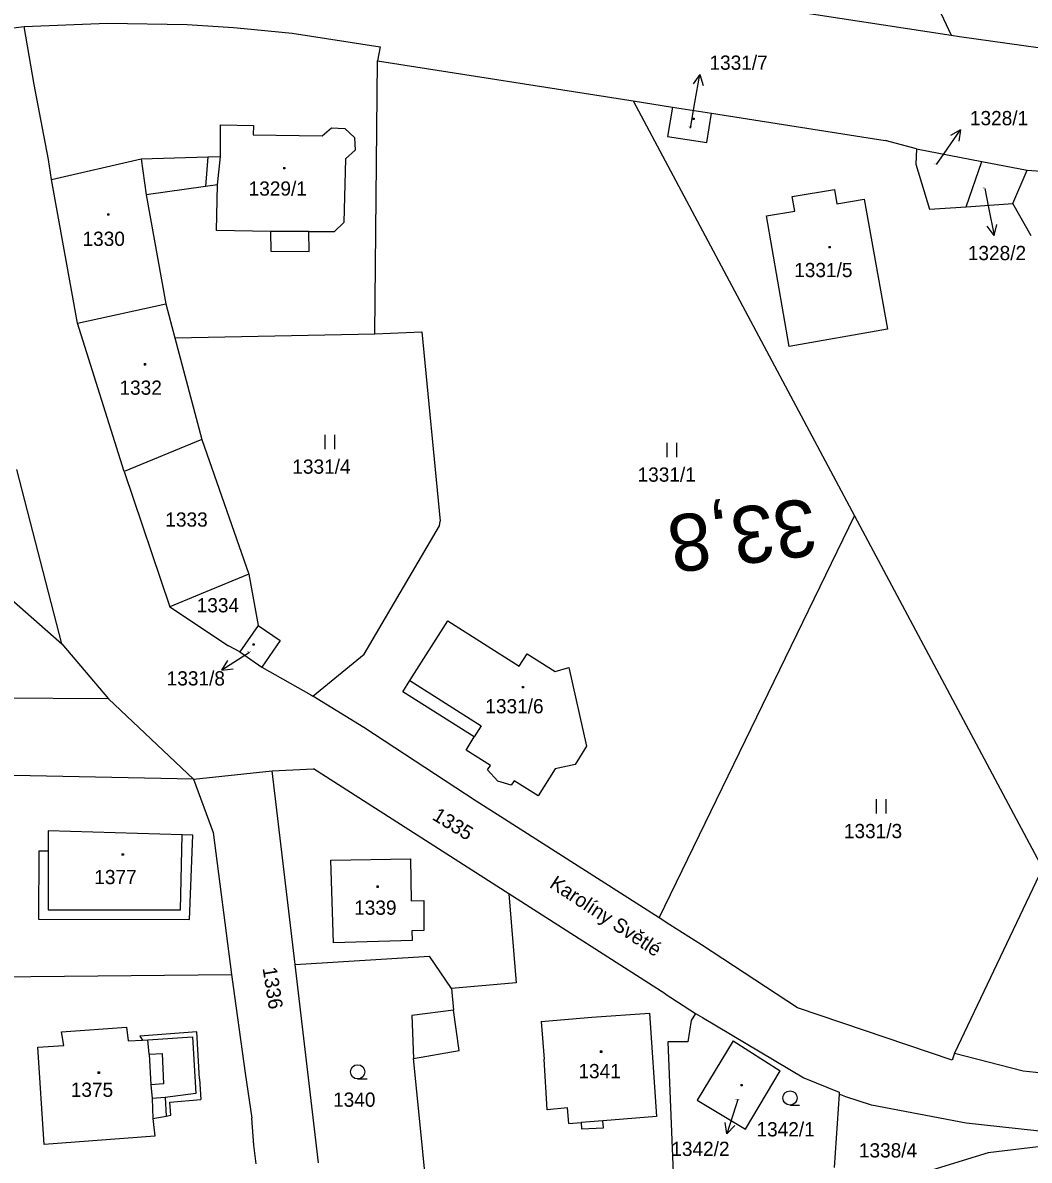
# Model space of a CAD drawing. Extents: x -805011 to -803920, y -1150790 to -1150234.
# Drawn here: x -804706.8 to -804600.8, y -1150469 to -1150349.3 of the extents above; entities that cross this region are included whole.
import ezdxf

# ---------------------------------------------------------------- set-up
doc = ezdxf.new("R2010")
doc.units = 0
for name, color, linetype in [('Default', 7, 'Continuous'), ('kilometráž - vrstava 7', 7, 'Continuous'), ('kn_celek - Cisla parcel pomocna', 7, 'Continuous'), ('kn_celek - Cisla pozemkovych parcel', 7, 'Continuous'), ('kn_celek - Cisla stavebnich parcel', 7, 'Continuous'), ('kn_celek - Dalsi prvky mapy popis', 7, 'Continuous'), ('kn_celek - Hranice parcel', 7, 'Continuous'), ('kn_celek - Vnitrni kresby', 7, 'Continuous'), ('kn_celek - Znacky budov', 7, 'Continuous'), ('kn_celek - Znacky kultur', 7, 'Continuous')]:
    doc.layers.add(name, color=color, linetype=linetype)

# ---------------------------------------------------------------- blocks, each defined once
blk = doc.blocks.new('306')
at = {"layer": 'Default'}
for p, q in [((-5.2, 0), (-5.2, 15)), ((4.8, 0), (4.8, 15))]:
    blk.add_line(p, q, dxfattribs=at)
blk = doc.blocks.new('304')
at = {"layer": 'Default'}
blk.add_line((-0.1, 0), (9.9, 0), dxfattribs=at)
blk.add_circle((-0.1, 7.5), 7.5, dxfattribs=at)
blk = doc.blocks.new('402')
at = {"layer": 'Default'}
for p, q in [((-0.8, 0.8), (0.7, 0.8)), ((-0.8, 0.8), (-0.8, -0.7)), ((0.7, 0.8), (0.7, -0.7)), ((0.7, -0.7), (-0.8, -0.7))]:
    blk.add_line(p, q, dxfattribs=at)
blk = doc.blocks.new('Z61')
at = {"layer": 'Default'}
for p, q in [((0, 0), (30, 0)), ((30, 0), (19.2, 5.3)), ((30, 0), (19.2, -5.3))]:
    blk.add_line(p, q, dxfattribs=at)

msp = doc.modelspace()

# ---------------------------------------------------------------- linework, layer by layer
at = {"layer": 'kn_celek - Cisla parcel pomocna'}
for p, q in [((-804636.49, -1150360.35), (-804636.01, -1150357.67)), ((-804610.59, -1150364.2), (-804609.77, -1150363.02)), ((-804605.49, -1150366.73), (-804605.1, -1150368.71)), ((-804682.9, -1150415.54), (-804683.3, -1150415.8)), ((-804631.49, -1150462.6), (-804631.74, -1150463.37))]:
    msp.add_line(p, q, dxfattribs=at)
at = {"layer": 'kn_celek - Hranice parcel'}
for p, q in [((-804636.63, -1150346.35), (-804609.04, -1150350.57)), ((-804610.97, -1150346.41), (-804609.04, -1150350.57)), ((-804716.89, -1150350.96), (-804706.62, -1150349.66)), ((-804706.62, -1150349.66), (-804697.86, -1150349.31)), ((-804705.57, -1150355.76), (-804706.62, -1150349.66)), ((-804697.86, -1150349.31), (-804689.48, -1150349.47)), ((-804689.48, -1150349.47), (-804684.61, -1150349.77)), ((-804684.61, -1150349.77), (-804683.48, -1150349.86)), ((-804683.48, -1150349.86), (-804678.43, -1150350.37)), ((-804678.43, -1150350.37), (-804669.14, -1150351.82)), ((-804609.04, -1150350.57), (-804608.15, -1150350.71)), ((-804608.15, -1150350.71), (-804597.6, -1150352.18)), ((-804669.14, -1150351.82), (-804669.43, -1150353.29)), ((-804669.7, -1150382.01), (-804669.43, -1150353.29)), ((-804669.43, -1150353.29), (-804642.5, -1150357.5)), ((-804705.03, -1150358.73), (-804705.57, -1150355.76)), ((-804642.5, -1150357.5), (-804638.39, -1150358.14)), ((-804642.5, -1150357.5), (-804619.21, -1150401.17)), ((-804638.39, -1150358.14), (-804638.89, -1150361.24)), ((-804638.39, -1150358.14), (-804634.27, -1150358.79)), ((-804704.08, -1150363.65), (-804705.03, -1150358.73)), ((-804634.75, -1150361.89), (-804634.27, -1150358.79)), ((-804634.27, -1150358.79), (-804615.97, -1150361.65)), ((-804638.89, -1150361.24), (-804634.75, -1150361.89)), ((-804612.68, -1150362.53), (-804615.97, -1150361.65)), ((-804612.68, -1150362.53), (-804612.74, -1150364.14)), ((-804612.68, -1150362.53), (-804605.79, -1150363.86)), ((-804703.74, -1150365.76), (-804704.08, -1150363.65)), ((-804703.74, -1150365.76), (-804694.3, -1150363.6)), ((-804694.3, -1150363.6), (-804693.79, -1150367.39)), ((-804612.74, -1150364.14), (-804611.3, -1150368.91)), ((-804607.45, -1150368.65), (-804605.79, -1150363.86)), ((-804605.79, -1150363.86), (-804601.03, -1150364.78)), ((-804602.54, -1150368.31), (-804601.03, -1150364.78)), ((-804601.03, -1150364.78), (-804583.56, -1150366.12)), ((-804701, -1150380.9), (-804703.74, -1150365.76)), ((-804693.79, -1150367.39), (-804691.72, -1150378.86)), ((-804625.77, -1150367.55), (-804621.33, -1150366.83)), ((-804625.5, -1150369.09), (-804625.77, -1150367.55)), ((-804621.33, -1150366.83), (-804621.06, -1150368.32)), ((-804621.06, -1150368.32), (-804618.19, -1150367.84)), ((-804618.19, -1150367.84), (-804615.74, -1150381.54)), ((-804628.48, -1150369.59), (-804625.5, -1150369.09)), ((-804611.3, -1150368.91), (-804607.45, -1150368.65)), ((-804607.45, -1150368.65), (-804602.54, -1150368.31)), ((-804600.6, -1150371.69), (-804602.54, -1150368.31)), ((-804626.08, -1150383.35), (-804628.48, -1150369.59)), ((-804701, -1150380.9), (-804691.72, -1150378.86)), ((-804691.72, -1150378.86), (-804690.78, -1150382.42)), ((-804696.11, -1150396.49), (-804701, -1150380.9)), ((-804690.78, -1150382.42), (-804669.7, -1150382.01)), ((-804669.7, -1150382.01), (-804664.75, -1150381.81)), ((-804664.75, -1150381.81), (-804662.85, -1150401.75)), ((-804615.74, -1150381.54), (-804626.08, -1150383.35)), ((-804690.78, -1150382.42), (-804687.93, -1150393.14)), ((-804687.93, -1150393.14), (-804696.11, -1150396.49)), ((-804687.93, -1150393.14), (-804682.98, -1150407.3)), ((-804702.68, -1150414.65), (-804707.42, -1150396.29)), ((-804696.11, -1150396.49), (-804691.29, -1150410.75)), ((-804639.79, -1150443.5), (-804619.21, -1150401.17)), ((-804619.21, -1150401.17), (-804599.42, -1150438.27)), ((-804670.83, -1150415.74), (-804662.92, -1150402.21)), ((-804662.92, -1150402.21), (-804662.85, -1150401.75)), ((-804682.98, -1150407.3), (-804684.18, -1150407.8)), ((-804682.98, -1150407.3), (-804681.98, -1150412.71)), ((-804684.18, -1150407.8), (-804688.58, -1150409.63)), ((-804708.84, -1150409.22), (-804702.68, -1150414.65)), ((-804688.58, -1150409.63), (-804691.29, -1150410.75)), ((-804691.29, -1150410.75), (-804685.13, -1150414.86)), ((-804666.02, -1150418.51), (-804662.04, -1150412.23)), ((-804662.04, -1150412.23), (-804654.51, -1150417.01)), ((-804681.98, -1150412.71), (-804683.93, -1150415.5)), ((-804681.98, -1150412.71), (-804679.67, -1150414.3)), ((-804702.68, -1150414.65), (-804697.76, -1150420.42)), ((-804679.67, -1150414.3), (-804681.62, -1150417.09)), ((-804683.93, -1150415.5), (-804685.13, -1150414.86)), ((-804683.93, -1150415.5), (-804681.62, -1150417.09)), ((-804676.25, -1150420.14), (-804670.83, -1150415.74)), ((-804654.51, -1150417.01), (-804653.68, -1150415.69)), ((-804653.68, -1150415.69), (-804650.71, -1150417.57)), ((-804681.62, -1150417.09), (-804676.44, -1150420.03)), ((-804650.71, -1150417.57), (-804649.28, -1150417.14)), ((-804649.28, -1150417.14), (-804647.42, -1150425.41)), ((-804666.77, -1150419.69), (-804666.02, -1150418.51)), ((-804697.76, -1150420.42), (-804721.63, -1150420.28)), ((-804688.79, -1150428.9), (-804697.76, -1150420.42)), ((-804676.44, -1150420.03), (-804676.25, -1150420.14)), ((-804670.86, -1150423.46), (-804676.25, -1150420.14)), ((-804659.26, -1150424.45), (-804666.77, -1150419.69)), ((-804659.05, -1150431.22), (-804670.86, -1150423.46)), ((-804660.1, -1150425.82), (-804659.26, -1150424.45)), ((-804647.42, -1150425.41), (-804648.63, -1150427.35)), ((-804657.55, -1150427.45), (-804660.1, -1150425.82)), ((-804680.52, -1150428), (-804676.16, -1150427.79)), ((-804655.59, -1150440.95), (-804676.16, -1150427.79)), ((-804657.86, -1150427.92), (-804657.55, -1150427.45)), ((-804650.71, -1150427.79), (-804652.53, -1150430.65)), ((-804648.63, -1150427.35), (-804650.71, -1150427.79)), ((-804688.79, -1150428.9), (-804710.95, -1150428.42)), ((-804688.79, -1150428.9), (-804680.52, -1150428)), ((-804688.79, -1150428.9), (-804686.75, -1150434.51)), ((-804678.11, -1150448.38), (-804680.52, -1150428)), ((-804656.76, -1150429.09), (-804657.86, -1150427.92)), ((-804655.06, -1150429.05), (-804655.35, -1150429.51)), ((-804652.53, -1150430.65), (-804655.06, -1150429.05)), ((-804655.35, -1150429.51), (-804656.76, -1150429.09)), ((-804656.45, -1150432.87), (-804659.05, -1150431.22)), ((-804639.79, -1150443.5), (-804656.45, -1150432.87)), ((-804704.09, -1150434.34), (-804704.1, -1150436.47)), ((-804690.01, -1150434.74), (-804704.09, -1150434.34)), ((-804688.87, -1150434.77), (-804690.01, -1150434.74)), ((-804689.21, -1150443.66), (-804688.87, -1150434.77)), ((-804686.75, -1150434.51), (-804684.79, -1150449.44)), ((-804705.1, -1150436.47), (-804705.11, -1150443.63)), ((-804704.1, -1150436.47), (-804705.1, -1150436.47)), ((-804599.42, -1150438.27), (-804608.69, -1150457.72)), ((-804639.15, -1150451.48), (-804655.59, -1150440.95)), ((-804655.59, -1150440.95), (-804654.84, -1150450.33)), ((-804705.11, -1150443.63), (-804689.21, -1150443.66)), ((-804638.64, -1150444.23), (-804639.79, -1150443.5)), ((-804635.32, -1150446.34), (-804638.64, -1150444.23)), ((-804625.2, -1150452.95), (-804635.32, -1150446.34)), ((-804678.11, -1150448.38), (-804663.96, -1150447.53)), ((-804661.65, -1150450.93), (-804663.96, -1150447.53)), ((-804675.65, -1150469.27), (-804678.11, -1150448.38)), ((-804710.75, -1150449.7), (-804684.79, -1150449.44)), ((-804684.79, -1150449.44), (-804683.38, -1150459.83)), ((-804654.84, -1150450.33), (-804661.65, -1150450.93)), ((-804661.65, -1150450.93), (-804661.44, -1150453.2)), ((-804639.15, -1150451.48), (-804635.94, -1150453.54)), ((-804608.93, -1150458.48), (-804625.2, -1150452.95)), ((-804661.44, -1150453.2), (-804665.82, -1150453.75)), ((-804665.82, -1150453.75), (-804665.63, -1150458.28)), ((-804635.94, -1150453.54), (-804636.41, -1150454.28)), ((-804635.94, -1150453.54), (-804635.23, -1150453.99)), ((-804635.23, -1150453.99), (-804624.56, -1150460.33)), ((-804636.41, -1150454.28), (-804636.77, -1150456.54)), ((-804636.77, -1150456.54), (-804638.87, -1150456.55)), ((-804638.87, -1150456.55), (-804638.3, -1150470.31)), ((-804631.98, -1150456.42), (-804635.78, -1150462.69)), ((-804631.98, -1150456.42), (-804627.05, -1150459.6)), ((-804608.69, -1150457.72), (-804608.93, -1150458.48)), ((-804608.69, -1150457.72), (-804601.47, -1150459.58)), ((-804664.84, -1150466.32), (-804665.63, -1150458.28)), ((-804683.38, -1150459.83), (-804682.67, -1150464.56)), ((-804630.7, -1150465.73), (-804627.05, -1150459.6)), ((-804601.47, -1150459.58), (-804584.21, -1150461.47)), ((-804624.56, -1150460.33), (-804620.82, -1150461.83)), ((-804620.84, -1150462.06), (-804621.34, -1150469.78)), ((-804620.82, -1150461.83), (-804620.84, -1150462.06)), ((-804620.14, -1150462.34), (-804620.84, -1150462.06)), ((-804617.42, -1150463.22), (-804620.14, -1150462.34)), ((-804635.78, -1150462.69), (-804630.7, -1150465.73)), ((-804607.47, -1150465.11), (-804617.42, -1150463.22)), ((-804682.45, -1150467.4), (-804682.67, -1150464.56)), ((-804592.74, -1150466.72), (-804607.47, -1150465.11)), ((-804664.29, -1150471.93), (-804664.84, -1150466.32)), ((-804592.74, -1150466.72), (-804605.13, -1150468.22)), ((-804682.2, -1150469.39), (-804682.45, -1150467.4)), ((-804605.13, -1150468.22), (-804622.06, -1150473.4))]:
    msp.add_line(p, q, dxfattribs=at)
at = {"layer": 'kn_celek - Vnitrni kresby'}
for p, q in [((-804685.97, -1150363.36), (-804685.96, -1150360.02)), ((-804685.96, -1150360.02), (-804682.49, -1150360.08)), ((-804682.49, -1150360.08), (-804682.51, -1150361.06)), ((-804675.26, -1150361.17), (-804674.26, -1150360.32)), ((-804674.26, -1150360.32), (-804672.87, -1150360.41)), ((-804672.87, -1150360.41), (-804671.87, -1150361.34)), ((-804682.51, -1150361.06), (-804675.26, -1150361.17)), ((-804671.87, -1150361.34), (-804671.77, -1150362.69)), ((-804671.77, -1150362.69), (-804672.8, -1150363.61)), ((-804694.3, -1150363.6), (-804687.28, -1150363.4)), ((-804687.28, -1150363.4), (-804687.53, -1150366.51)), ((-804687.28, -1150363.4), (-804685.97, -1150363.36)), ((-804686.26, -1150366.33), (-804685.97, -1150363.36)), ((-804672.8, -1150363.61), (-804672.99, -1150370.31)), ((-804687.53, -1150366.51), (-804693.79, -1150367.39)), ((-804686.26, -1150366.33), (-804687.53, -1150366.51)), ((-804686.37, -1150371.14), (-804686.26, -1150366.33)), ((-804672.99, -1150370.31), (-804673.97, -1150371.26)), ((-804680.69, -1150371.24), (-804686.37, -1150371.14)), ((-804676.66, -1150371.25), (-804680.69, -1150371.24)), ((-804680.69, -1150371.24), (-804680.67, -1150373.32)), ((-804676.63, -1150373.35), (-804676.66, -1150371.25)), ((-804676.66, -1150371.25), (-804673.97, -1150371.26)), ((-804680.67, -1150373.32), (-804676.63, -1150373.35)), ((-804666.02, -1150418.51), (-804658.51, -1150423.27)), ((-804658.51, -1150423.27), (-804659.26, -1150424.45)), ((-804690.19, -1150442.65), (-804690.01, -1150434.74)), ((-804704.1, -1150436.47), (-804704.12, -1150442.63)), ((-804674.33, -1150437.42), (-804665.97, -1150437.27)), ((-804674.08, -1150446.1), (-804674.33, -1150437.42)), ((-804665.97, -1150437.27), (-804665.89, -1150441.68)), ((-804665.89, -1150441.68), (-804664.55, -1150441.65)), ((-804664.55, -1150441.65), (-804664.56, -1150444.81)), ((-804704.12, -1150442.63), (-804690.19, -1150442.65)), ((-804664.56, -1150444.81), (-804665.81, -1150444.84)), ((-804665.81, -1150444.84), (-804665.78, -1150445.86)), ((-804665.78, -1150445.86), (-804674.08, -1150446.1)), ((-804660.82, -1150457.45), (-804661.44, -1150453.2)), ((-804652.21, -1150454.41), (-804646.87, -1150453.95)), ((-804646.87, -1150453.95), (-804640.78, -1150453.51)), ((-804640.78, -1150453.51), (-804640.04, -1150464.41)), ((-804702.69, -1150455.5), (-804695.87, -1150455)), ((-804695.87, -1150455), (-804695.69, -1150456.44)), ((-804652.21, -1150454.41), (-804651.89, -1150458.37)), ((-804702.47, -1150456.92), (-804702.69, -1150455.5)), ((-804695.69, -1150456.44), (-804694.16, -1150456.37)), ((-804688.44, -1150455.5), (-804694.45, -1150455.95)), ((-804694.45, -1150455.95), (-804694.16, -1150456.37)), ((-804694.16, -1150456.37), (-804693.61, -1150456.33)), ((-804693.61, -1150456.33), (-804688.91, -1150456.02)), ((-804693.48, -1150457.82), (-804693.61, -1150456.33)), ((-804688.91, -1150456.02), (-804688.56, -1150461.98)), ((-804688.16, -1150460.44), (-804688.44, -1150455.5)), ((-804705.18, -1150457.11), (-804702.47, -1150456.92)), ((-804704.52, -1150467.35), (-804705.18, -1150457.11)), ((-804693.48, -1150457.82), (-804692.1, -1150457.75)), ((-804692.1, -1150457.75), (-804691.95, -1150460.97)), ((-804665.63, -1150458.28), (-804660.82, -1150457.45)), ((-804693.48, -1150457.82), (-804693.3, -1150461.06)), ((-804651.58, -1150463.71), (-804651.89, -1150458.37)), ((-804691.95, -1150460.97), (-804693.3, -1150461.06)), ((-804693.3, -1150461.06), (-804693.16, -1150462.5)), ((-804688.16, -1150460.44), (-804688.04, -1150462.61)), ((-804691.77, -1150462.41), (-804693.16, -1150462.5)), ((-804693.16, -1150462.5), (-804693.07, -1150464.61)), ((-804688.56, -1150461.98), (-804691.77, -1150462.41)), ((-804691.77, -1150462.41), (-804691.68, -1150464.36)), ((-804691.28, -1150462.87), (-804688.04, -1150462.61)), ((-804691.18, -1150464.27), (-804691.28, -1150462.87)), ((-804649.44, -1150463.49), (-804651.58, -1150463.71)), ((-804649.3, -1150465.12), (-804649.44, -1150463.49)), ((-804693.07, -1150464.61), (-804691.68, -1150464.36)), ((-804693.07, -1150464.61), (-804692.87, -1150466.46)), ((-804691.68, -1150464.36), (-804691.18, -1150464.27)), ((-804645.7, -1150464.86), (-804648, -1150465.03)), ((-804640.04, -1150464.41), (-804645.7, -1150464.86)), ((-804645.65, -1150465.59), (-804645.7, -1150464.86)), ((-804649.3, -1150465.12), (-804648, -1150465.03)), ((-804648, -1150465.03), (-804647.95, -1150465.69)), ((-804647.95, -1150465.69), (-804645.65, -1150465.59)), ((-804692.87, -1150466.46), (-804704.52, -1150467.35))]:
    msp.add_line(p, q, dxfattribs=at)

# ---------------------------------------------------------------- block references
at = {"layer": 'kn_celek - Cisla parcel pomocna'}
for p, xscale, yscale, rotation in [((-804636.01, -1150357.67), 0.10000000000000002, 0.1, 79.82946000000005), ((-804609.77, -1150363.02), 0.1, 0.09999999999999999, 55.19853000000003), ((-804605.1, -1150368.71), 0.1, 0.10000000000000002, -78.84683999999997), ((-804683.3, -1150415.8), 0.1, 0.09999999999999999, -147.17592), ((-804631.74, -1150463.37), 0.09999999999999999, 0.09999999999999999, -107.86491)]:
    msp.add_blockref('Z61', p, dxfattribs=dict(at, xscale=xscale, yscale=yscale, rotation=rotation))
at = {"layer": 'kn_celek - Znacky budov', "xscale": 0.1, "yscale": 0.10000000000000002}
for p in [(-804636.16, -1150359.38), (-804679.25, -1150364.59), (-804697.78, -1150369.47), (-804621.83, -1150372.91), (-804693.92, -1150385.23), (-804682.47, -1150414.71), (-804654.12, -1150419.21), (-804696.26, -1150436.82), (-804669.43, -1150440.21), (-804645.9, -1150457.58), (-804698.78, -1150459.79), (-804631.11, -1150461.11)]:
    msp.add_blockref('402', p, dxfattribs=at)
at = {"layer": 'kn_celek - Znacky kultur', "xscale": 0.1, "yscale": 0.10000000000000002}
for name, p in [('306', (-804674.41, -1150394.14)), ('306', (-804638.41, -1150394.98)), ('306', (-804616.37, -1150432.5)), ('304', (-804671.51, -1150460.44)), ('304', (-804625.99, -1150463.19))]:
    msp.add_blockref(name, p, dxfattribs=at)

# ---------------------------------------------------------------- texts
at = {"layer": 'kilometráž - vrstava 7'}
msp.add_text('33,8', height=6, rotation=187.1506, dxfattribs=at).set_placement((-804623.64, -1150399.3))
at = {"layer": 'kn_celek - Cisla parcel pomocna'}
for s, p in [('1331/7', (-804634.48, -1150354.22)), ('1328/1', (-804607.06, -1150360.06)), ('1328/2', (-804607.28, -1150374.26)), ('1331/8', (-804691.63, -1150419.03)), ('1342/2', (-804638.5, -1150468.55))]:
    msp.add_text(s, height=1.5, dxfattribs=at).set_placement(p)
at = {"layer": 'kn_celek - Cisla pozemkovych parcel'}
for s, height, p in [('1328/1', 0.1, (-804610.84, -1150364.17)), ('1328/2', 0.1, (-804605.76, -1150366.7)), ('1331/4', 1.5, (-804678.4, -1150396.74)), ('1331/1', 1.5, (-804642.05, -1150397.58)), ('1333', 1.5, (-804691.77, -1150402.31)), ('1334', 1.5, (-804688.47, -1150411.33)), ('1331/3', 1.5, (-804620.33, -1150435.1)), ('1340', 1.5, (-804674.11, -1150463.37)), ('1342/1', 1.5, (-804629.53, -1150466.49)), ('1338/4', 1.5, (-804618.75, -1150468.71))]:
    msp.add_text(s, height=height, dxfattribs=at).set_placement(p)
for s, rotation, p in [('1335', 328.5, (-804663.77, -1150433.07)), ('1336', 279, (-804681.54, -1150448.78))]:
    msp.add_text(s, height=1.5, rotation=rotation, dxfattribs=at).set_placement(p)
at = {"layer": 'kn_celek - Cisla stavebnich parcel'}
for s, height, p in [('1331/7', 0.1, (-804636.75, -1150360.32)), ('1329/1', 1.5, (-804683, -1150367.47)), ('1330', 1.5, (-804700.49, -1150372.76)), ('1331/5', 1.5, (-804625.56, -1150376.05)), ('1332', 1.5, (-804696.6, -1150388.43)), ('1331/8', 0.1, (-804683.16, -1150415.51)), ('1331/6', 1.5, (-804658.08, -1150421.96)), ('1377', 1.5, (-804699.25, -1150439.94)), ('1339', 1.5, (-804671.89, -1150443.16)), ('1341', 1.5, (-804648.28, -1150460.37)), ('1375', 1.5, (-804701.73, -1150462.33)), ('1342/2', 0.1, (-804631.76, -1150462.65))]:
    msp.add_text(s, height=height, dxfattribs=at).set_placement(p)
at = {"layer": 'kn_celek - Dalsi prvky mapy popis'}
msp.add_text('Karolíny Světlé', height=1.5, rotation=326.5274, dxfattribs=at).set_placement((-804651.42, -1150440.2))

doc.saveas('drawing.dxf')
